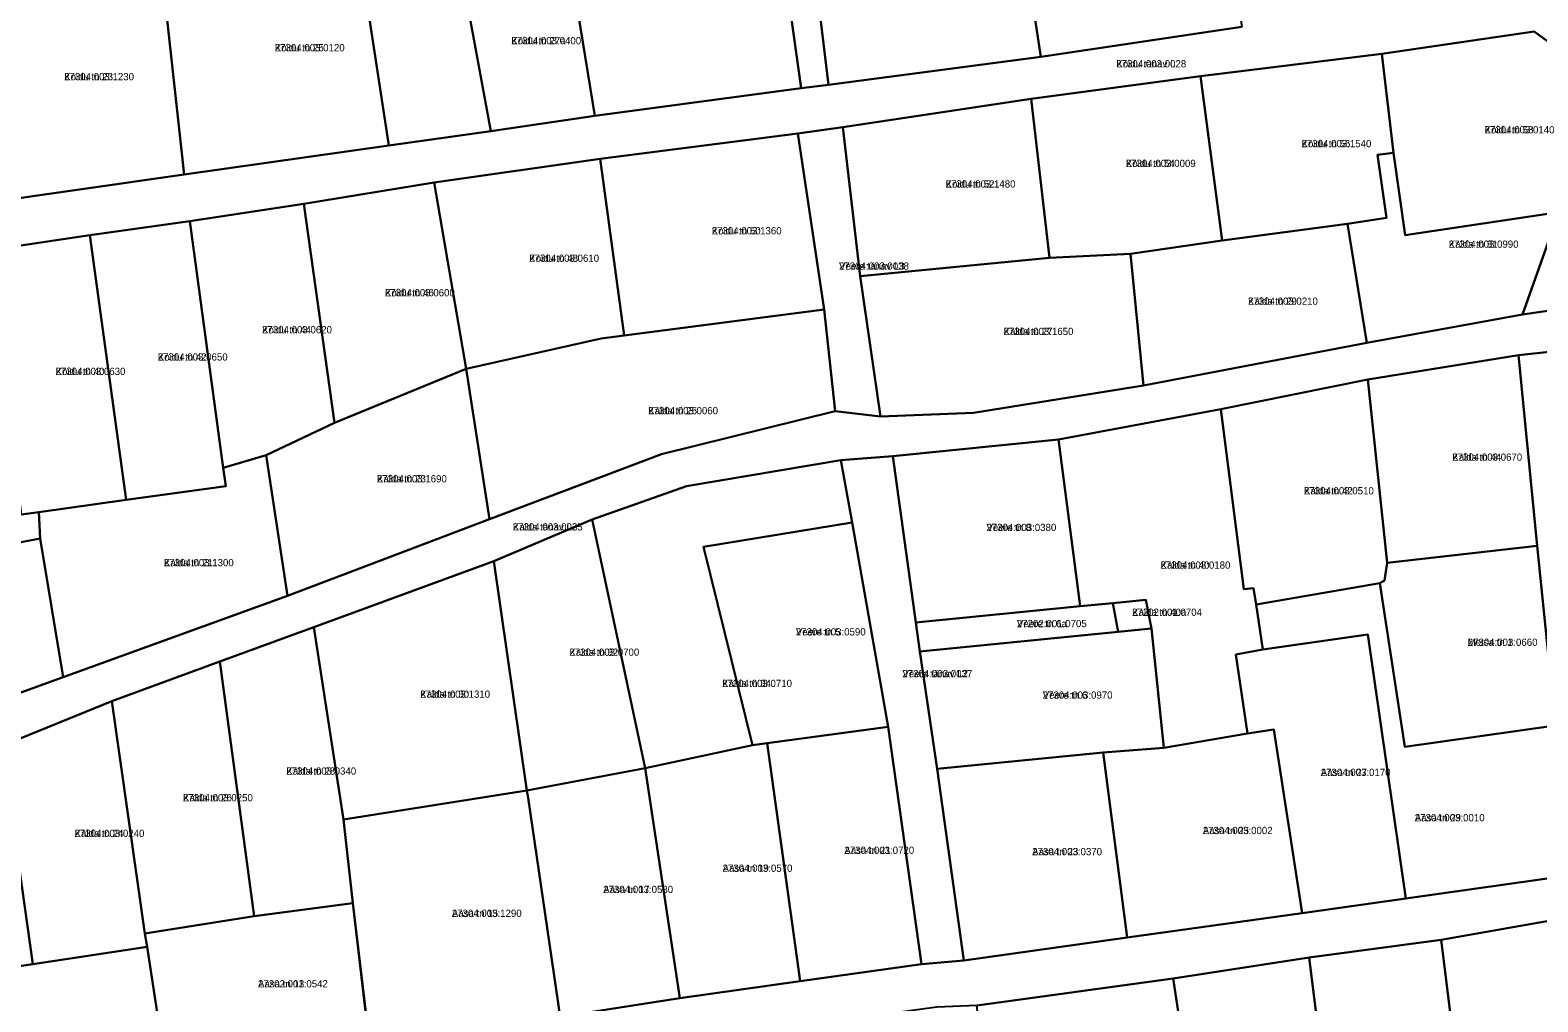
# Model space of a CAD drawing. Extents: x 603789 to 628102, y 6569852 to 6597259.
# Drawn here: x 622067.3 to 622380.3, y 6579875.4 to 6580077.1 of the extents above; entities that cross this region are included whole.
import ezdxf

# ---------------------------------------------------------------- set-up
doc = ezdxf.new("R2010")
doc.units = 0
for name, color, linetype in [('L_AADRESS', 7, 'Continuous'), ('PIIR', 7, 'Continuous'), ('TUNNUS', 7, 'Continuous')]:
    doc.layers.add(name, color=color, linetype=linetype)

msp = doc.modelspace()

# ---------------------------------------------------------------- linework, layer by layer
at = {"layer": 'PIIR'}
for points in [[(622214.59, 6580147.62), (622221.28, 6580148.11), (622228.9, 6580100.11), (622233.04, 6580065.71), (622227.37, 6580065.07), (622222.58, 6580099.13)], [(622277.13, 6580071.57), (622271.8, 6580106.62), (622283.22, 6580108.54), (622309.96, 6580112.73), (622313.46, 6580113.3), (622318.87, 6580077.76)], [(622228.9, 6580100.11), (622255.74, 6580104.17), (622271.8, 6580106.62), (622277.13, 6580071.57), (622233.04, 6580065.71)], [(622136.86, 6580085.29), (622135.11, 6580098.05), (622140.05, 6580098.93), (622149.89, 6580100.76), (622153, 6580079.6), (622158.48, 6580080.5), (622162.96, 6580056.12), (622141.79, 6580053.15)], [(622162.96, 6580056.12), (622158.48, 6580080.5), (622153, 6580079.6), (622149.89, 6580100.76), (622165.46, 6580103.12), (622168.68, 6580081.93), (622180.63, 6580083.57), (622184.54, 6580059.28)], [(622099.29, 6580047.14), (622094.42, 6580091.26), (622110.47, 6580094.49), (622135.11, 6580098.05), (622136.86, 6580085.29), (622141.79, 6580053.15)], [(622180.63, 6580083.57), (622179.2, 6580093.14), (622200.52, 6580096.06), (622222.58, 6580099.13), (622227.37, 6580065.07), (622184.54, 6580059.28)], [(622050.17, 6580081.18), (622049.46, 6580088.32), (622080.81, 6580090.17), (622094.42, 6580091.26), (622099.29, 6580047.14), (622056.23, 6580041.01)], [(622384.68, 6580039.3), (622352.79, 6580034.53), (622350.39, 6580051.64), (622347.93, 6580072.15), (622379.53, 6580076.81), (622388.32, 6580070.36), (622390.48, 6580063.22)], [(622388.32, 6580070.36), (622404.75, 6580076.68), (622386.22, 6580019.4), (622377.13, 6580018.08), (622384.68, 6580039.3), (622390.48, 6580063.22)], [(622310.32, 6580067.53), (622347.93, 6580072.15), (622350.39, 6580051.64), (622347.03, 6580051.18), (622348.89, 6580038.11), (622340.78, 6580036.89), (622314.82, 6580033.45)], [(622275.16, 6580062.82), (622310.32, 6580067.53), (622314.82, 6580033.45), (622295.73, 6580030.7), (622278.92, 6580029.84)], [(622236.04, 6580056.96), (622275.16, 6580062.82), (622278.92, 6580029.84), (622239.65, 6580026.01)], [(622226.68, 6580055.67), (622236.04, 6580056.96), (622239.65, 6580026.01), (622243.83, 6579996.94), (622234.46, 6579997.99), (622232.16, 6580019.13)], [(622185.69, 6580050.36), (622226.68, 6580055.67), (622232.16, 6580019.13), (622190.64, 6580013.73)], [(622151.21, 6580045.48), (622185.69, 6580050.36), (622190.64, 6580013.73), (622185.87, 6580013.1), (622157.82, 6580006.81)], [(622340.78, 6580036.89), (622348.89, 6580038.11), (622347.03, 6580051.18), (622350.39, 6580051.64), (622352.79, 6580034.53), (622384.68, 6580039.3), (622377.13, 6580018.08), (622344.82, 6580012.21)], [(622130.5, 6579995.61), (622124.15, 6580041.03), (622151.21, 6580045.48), (622157.82, 6580006.81)], [(622107.4, 6579986.23), (622100.44, 6580037.44), (622124.15, 6580041.03), (622130.5, 6579995.61), (622116.3, 6579988.88)], [(622065.47, 6579976.6), (622062.62, 6579999.36), (622057.94, 6580031.28), (622079.7, 6580034.57), (622087.26, 6579979.6), (622069.13, 6579977.07)], [(622079.7, 6580034.57), (622100.44, 6580037.44), (622107.4, 6579986.23), (622107.94, 6579982.47), (622087.26, 6579979.6)], [(622344.82, 6580012.21), (622298.46, 6580003.31), (622295.73, 6580030.7), (622314.82, 6580033.45), (622340.78, 6580036.89)], [(622243.83, 6579996.94), (622239.65, 6580026.01), (622278.92, 6580029.84), (622295.73, 6580030.7), (622298.46, 6580003.31), (622263.18, 6579997.65)], [(622234.46, 6579997.99), (622198.41, 6579989.12), (622162.65, 6579975.63), (622157.82, 6580006.81), (622185.87, 6580013.1), (622190.64, 6580013.73), (622232.16, 6580019.13)], [(622345, 6580004.56), (622376.29, 6580009.62), (622380.15, 6579970.05), (622349.03, 6579966.52)], [(622376.29, 6580009.62), (622385.91, 6580010.68), (622390.65, 6579963.73), (622393.58, 6579933.8), (622397.18, 6579904.18), (622387.67, 6579901.78), (622383.97, 6579932.75), (622380.15, 6579970.05)], [(622116.3, 6579988.88), (622130.5, 6579995.61), (622157.82, 6580006.81), (622162.65, 6579975.63), (622120.75, 6579959.66)], [(622321.3, 6579961.3), (622319.27, 6579961.1), (622314.51, 6579998.44), (622345, 6580004.56), (622349.03, 6579966.52), (622348.46, 6579962.9), (622347.52, 6579962.31), (622321.87, 6579957.9)], [(622024.91, 6579994.79), (622062.62, 6579999.36), (622065.47, 6579976.6), (622069.13, 6579977.07), (622069.41, 6579971.62), (622029.25, 6579963.89)], [(622300.12, 6579952.94), (622298.91, 6579958.85), (622292.11, 6579958.2), (622285.32, 6579957.57), (622280.78, 6579992.17), (622314.51, 6579998.44), (622319.27, 6579961.1), (622321.3, 6579961.3), (622321.87, 6579957.9), (622323.22, 6579948.53), (622317.6, 6579947.55), (622320.02, 6579931.09), (622302.65, 6579928.18)], [(622246.41, 6579988.7), (622280.78, 6579992.17), (622285.32, 6579957.57), (622251.18, 6579954.13)], [(622074.15, 6579942.81), (622069.41, 6579971.62), (622069.13, 6579977.07), (622087.26, 6579979.6), (622107.94, 6579982.47), (622107.4, 6579986.23), (622116.3, 6579988.88), (622120.75, 6579959.66)], [(622183.97, 6579975.52), (622203.61, 6579982.45), (622235.64, 6579987.85), (622238, 6579974.94), (622207.1, 6579969.89), (622217.3, 6579928.7), (622194.97, 6579923.91)], [(622235.64, 6579987.85), (622246.41, 6579988.7), (622251.18, 6579954.13), (622251.99, 6579948.17), (622255.63, 6579923.76), (622261.19, 6579884.01), (622252.37, 6579883.22), (622245.46, 6579932.48), (622238, 6579974.94)], [(622163.58, 6579966.88), (622183.97, 6579975.52), (622194.97, 6579923.91), (622170.43, 6579919.31)], [(622217.3, 6579928.7), (622207.1, 6579969.89), (622238, 6579974.94), (622245.46, 6579932.48), (622220.33, 6579929.13)], [(622029.25, 6579963.89), (622069.41, 6579971.62), (622074.15, 6579942.81), (622034.01, 6579928.32)], [(622347.52, 6579962.31), (622348.46, 6579962.9), (622349.03, 6579966.52), (622380.15, 6579970.05), (622383.97, 6579932.75), (622352.72, 6579928.37)], [(622126.18, 6579953.17), (622163.58, 6579966.88), (622170.43, 6579919.31), (622132.4, 6579913.28)], [(622345.02, 6579951.64), (622323.22, 6579948.53), (622321.87, 6579957.9), (622347.52, 6579962.31), (622352.72, 6579928.37), (622383.97, 6579932.75), (622387.67, 6579901.78), (622352.89, 6579896.87)], [(622251.99, 6579948.17), (622251.18, 6579954.13), (622285.32, 6579957.57), (622292.11, 6579958.2), (622293.2, 6579952.24)], [(622293.2, 6579952.24), (622292.11, 6579958.2), (622298.91, 6579958.85), (622300.12, 6579952.94)], [(622106.73, 6579946.04), (622126.18, 6579953.17), (622132.4, 6579913.28), (622134.28, 6579895.91), (622113.84, 6579893.19)], [(622251.99, 6579948.17), (622293.2, 6579952.24), (622300.12, 6579952.94), (622302.65, 6579928.18), (622290.11, 6579927.16), (622255.63, 6579923.76)], [(622320.02, 6579931.09), (622317.6, 6579947.55), (622323.22, 6579948.53), (622345.02, 6579951.64), (622352.89, 6579896.87), (622331.41, 6579893.82), (622325.5, 6579931.98)], [(622084.25, 6579937.86), (622106.73, 6579946.04), (622113.84, 6579893.19), (622091.14, 6579889.62)], [(622061.48, 6579928.59), (622084.25, 6579937.86), (622091.14, 6579889.62), (622091.61, 6579886.88), (622067.85, 6579883.26)], [(622220.33, 6579929.13), (622245.46, 6579932.48), (622252.37, 6579883.22), (622227.17, 6579879.74)], [(622295.06, 6579888.8), (622290.11, 6579927.16), (622302.65, 6579928.18), (622320.02, 6579931.09), (622325.5, 6579931.98), (622331.41, 6579893.82)], [(622034.9, 6579918.24), (622061.48, 6579928.59), (622067.85, 6579883.26), (622040.03, 6579879.14)], [(622202.17, 6579876.21), (622194.97, 6579923.91), (622217.3, 6579928.7), (622220.33, 6579929.13), (622227.17, 6579879.74)], [(622261.19, 6579884.01), (622255.63, 6579923.76), (622290.11, 6579927.16), (622295.06, 6579888.8)], [(622170.72, 6579917.77), (622170.43, 6579919.31), (622194.97, 6579923.91), (622202.17, 6579876.21), (622177.32, 6579872.32)], [(622134.28, 6579895.91), (622132.4, 6579913.28), (622170.43, 6579919.31), (622170.72, 6579917.77), (622177.32, 6579872.32), (622137.73, 6579866.98)], [(622095.55, 6579860.95), (622091.61, 6579886.88), (622091.14, 6579889.62), (622113.84, 6579893.19), (622134.28, 6579895.91), (622136.98, 6579873.27), (622137.73, 6579866.98)], [(622360.27, 6579888.32), (622399.48, 6579895.23), (622401.63, 6579868.51), (622396.67, 6579867.81), (622363.4, 6579863.22)], [(622332.84, 6579884.63), (622360.27, 6579888.32), (622363.4, 6579863.22), (622365.62, 6579845.6), (622338.16, 6579841.8)], [(622091.61, 6579886.88), (622095.55, 6579860.95), (622044.62, 6579854.13), (622040.03, 6579879.14), (622067.85, 6579883.26)], [(622311.03, 6579837.93), (622304.61, 6579880.29), (622332.84, 6579884.63), (622338.16, 6579841.8)], [(622263.84, 6579874.66), (622304.61, 6579880.29), (622311.03, 6579837.93), (622315.01, 6579803.58), (622273.45, 6579797.29)]]:
    msp.add_lwpolyline(points, close=True, dxfattribs=at)
for points in [[(622405.95, 6580090.22), (622404.75, 6580076.68), (622388.32, 6580070.36), (622379.53, 6580076.81), (622347.93, 6580072.15), (622310.32, 6580067.53), (622275.16, 6580062.82), (622236.04, 6580056.96), (622226.68, 6580055.67), (622185.69, 6580050.36), (622151.21, 6580045.48), (622124.15, 6580041.03), (622100.44, 6580037.44), (622079.7, 6580034.57), (622057.94, 6580031.28)], [(622056.23, 6580041.01), (622099.29, 6580047.14), (622141.79, 6580053.15), (622162.96, 6580056.12), (622184.54, 6580059.28), (622227.37, 6580065.07), (622233.04, 6580065.71), (622277.13, 6580071.57), (622318.87, 6580077.76)], [(622034.01, 6579928.32), (622074.15, 6579942.81), (622120.75, 6579959.66), (622162.65, 6579975.63), (622198.41, 6579989.12), (622234.46, 6579997.99), (622243.83, 6579996.94), (622263.18, 6579997.65), (622298.46, 6580003.31), (622344.82, 6580012.21), (622377.13, 6580018.08), (622386.22, 6580019.4)], [(622385.91, 6580010.68), (622376.29, 6580009.62), (622345, 6580004.56), (622314.51, 6579998.44), (622280.78, 6579992.17), (622246.41, 6579988.7), (622235.64, 6579987.85), (622203.61, 6579982.45), (622183.97, 6579975.52), (622163.58, 6579966.88), (622126.18, 6579953.17), (622106.73, 6579946.04), (622084.25, 6579937.86), (622061.48, 6579928.59)], [(622044.62, 6579854.13), (622095.55, 6579860.95), (622137.73, 6579866.98), (622177.32, 6579872.32), (622202.17, 6579876.21), (622227.17, 6579879.74), (622252.37, 6579883.22), (622261.19, 6579884.01), (622295.06, 6579888.8), (622331.41, 6579893.82), (622352.89, 6579896.87), (622387.67, 6579901.78)], [(622399.48, 6579895.23), (622360.27, 6579888.32), (622332.84, 6579884.63), (622304.61, 6579880.29), (622263.84, 6579874.66), (622255.58, 6579874.31), (622212.9, 6579868.55), (622134.92, 6579857.44), (622090.44, 6579850.56), (621961.56, 6579835.58)]]:
    msp.add_lwpolyline(points, dxfattribs=at)

# ---------------------------------------------------------------- texts
at = {"layer": 'L_AADRESS'}
for s, p in [('Koidu tn 27a', (622167.21, 6580074.16)), ('Koidu tn 25', (622118.11, 6580072.7)), ('Koidu tänav L2', (622292.82, 6580069.36)), ('Koidu tn 23', (622074.38, 6580066.69)), ('Koidu tn 58', (622369.28, 6580055.67)), ('Koidu tn 56', (622331.26, 6580052.8)), ('Koidu tn 54', (622294.79, 6580048.69)), ('Koidu tn 52', (622257.38, 6580044.42)), ('Koidu tn 50', (622208.82, 6580034.7)), ('Kalda tn 31', (622361.82, 6580031.93)), ('Koidu tn 48', (622170.93, 6580029.01)), ('Veere tänav L3', (622235.25, 6580027.38)), ('Koidu tn 46', (622140.98, 6580021.85)), ('Kalda tn 29', (622320.16, 6580020.1)), ('Koidu tn 44', (622115.47, 6580014.17)), ('Kalda tn 27', (622269.41, 6580013.82)), ('Koidu tn 42', (622093.82, 6580008.52)), ('Koidu tn 40', (622072.6, 6580005.53)), ('Kalda tn 25', (622195.63, 6579997.38)), ('Kalda tn 44', (622362.57, 6579987.73)), ('Kalda tn 23', (622139.32, 6579983.24)), ('Kalda tn 42', (622331.77, 6579980.75)), ('Kalda tänav L2', (622167.52, 6579973.26)), ('Veere tn 8', (622265.86, 6579973.14)), ('Kalda tn 21', (622095.08, 6579965.84)), ('Kalda tn 40', (622302, 6579965.33)), ('Kalda tn 40a', (622296.09, 6579955.54)), ('Veere tn 5', (622226.28, 6579951.47)), ('Veere tn 6a', (622272.17, 6579953.19)), ('Metsa tn 1', (622365.75, 6579949.31)), ('Kalda tn 32', (622179.27, 6579947.25)), ('Veere tänav L2', (622248.41, 6579942.79)), ('Kalda tn 34', (622210.98, 6579940.77)), ('Kalda tn 30', (622148.3, 6579938.54)), ('Veere tn 6', (622277.53, 6579938.35)), ('Kalda tn 28', (622120.5, 6579922.58)), ('Aasa tn 27', (622335.25, 6579922.31)), ('Kalda tn 26', (622099.05, 6579917.05)), ('Aasa tn 29', (622354.77, 6579912.9)), ('Kalda tn 24', (622076.54, 6579909.65)), ('Aasa tn 25', (622310.76, 6579910.25)), ('Aasa tn 21', (622236.35, 6579906.14)), ('Aasa tn 23', (622275.35, 6579905.86)), ('Aasa tn 19', (622211.07, 6579902.42)), ('Aasa tn 17', (622186.3, 6579898.01)), ('Aasa tn 15', (622154.86, 6579893.07)), ('Aasa tn 13', (622114.63, 6579878.43))]:
    msp.add_text(s, height=1.5, dxfattribs=at).set_placement(p)
at = {"layer": 'TUNNUS'}
for s, p in [('27304:003:0400', (622167.21, 6580074.16)), ('27304:003:0120', (622118.11, 6580072.7)), ('27304:003:0028', (622292.82, 6580069.36)), ('27304:003:1230', (622074.38, 6580066.69)), ('27304:003:0140', (622369.28, 6580055.67)), ('27304:003:1540', (622331.26, 6580052.8)), ('27304:003:0009', (622294.79, 6580048.69)), ('27304:003:1480', (622257.38, 6580044.42)), ('27304:003:1360', (622208.82, 6580034.7)), ('27304:003:0990', (622361.82, 6580031.93)), ('27304:003:0610', (622170.93, 6580029.01)), ('27304:003:0038', (622235.25, 6580027.38)), ('27304:003:0600', (622140.98, 6580021.85)), ('27304:003:0210', (622320.16, 6580020.1)), ('27304:003:0620', (622115.47, 6580014.17)), ('27304:003:1650', (622269.41, 6580013.82)), ('27304:003:0650', (622093.82, 6580008.52)), ('27304:003:0630', (622072.6, 6580005.53)), ('27304:003:0060', (622195.63, 6579997.38)), ('27304:003:0670', (622362.57, 6579987.73)), ('27304:003:1690', (622139.32, 6579983.24)), ('27304:003:0510', (622331.77, 6579980.75)), ('27304:003:0035', (622167.52, 6579973.26)), ('27304:003:0380', (622265.86, 6579973.14)), ('27304:003:1300', (622095.08, 6579965.84)), ('27304:003:0180', (622302, 6579965.33)), ('27202:001:0704', (622296.09, 6579955.54)), ('27304:003:0590', (622226.28, 6579951.47)), ('27202:001:0705', (622272.17, 6579953.19)), ('27304:003:0660', (622365.75, 6579949.31)), ('27304:003:0700', (622179.27, 6579947.25)), ('27304:003:0037', (622248.41, 6579942.79)), ('27304:003:0710', (622210.98, 6579940.77)), ('27304:003:1310', (622148.3, 6579938.54)), ('27304:003:0970', (622277.53, 6579938.35)), ('27304:003:0340', (622120.5, 6579922.58)), ('27304:003:0170', (622335.25, 6579922.31)), ('27304:003:0250', (622099.05, 6579917.05)), ('27304:003:0010', (622354.77, 6579912.9)), ('27304:003:0240', (622076.54, 6579909.65)), ('27304:003:0002', (622310.76, 6579910.25)), ('27304:003:0720', (622236.35, 6579906.14)), ('27304:003:0370', (622275.35, 6579905.86)), ('27304:003:0570', (622211.07, 6579902.42)), ('27304:003:0580', (622186.3, 6579898.01)), ('27304:003:1290', (622154.86, 6579893.07)), ('27202:001:0542', (622114.63, 6579878.43))]:
    msp.add_text(s, height=1.5, dxfattribs=at).set_placement(p)

doc.saveas('drawing.dxf')
